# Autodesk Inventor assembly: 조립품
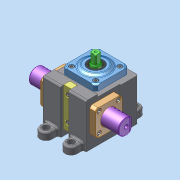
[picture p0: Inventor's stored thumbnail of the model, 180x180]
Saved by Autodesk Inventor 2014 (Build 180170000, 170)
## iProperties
Created: 2024-11
Part Number: 조립품
Document SubType Name: Assembly
Designer: dg
Author: dg
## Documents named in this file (10)
- C:\Users\dg\Desktop\741104V1008\조립품.iam
- C:\Users\dg\Desktop\741104V1008\본체.ipt
- C:\Users\dg\Desktop\741104V1008\가져온 구성요소\피니언 축\피니언 축.ipt
- C:\Users\dg\Desktop\741104V1008\가져온 구성요소\깊음 홈 볼 베어링 6202\깊음 홈 볼 베어링 6202.ipt
- C:\Users\dg\Desktop\741104V1008\가져온 구성요소\커버\커버.ipt
- C:\Users\dg\Desktop\741104V1008\가져온 구성요소\오일 실 15 25 4\오일 실 15 25 4.ipt
- C:\Users\dg\Desktop\741104V1008\가져온 구성요소\육각 소켓 머리 볼트 M4x10\육각 소켓 머리 볼트 M4x10.ipt
- C:\Users\dg\Desktop\741104V1008\가져온 구성요소\수지 부시\수지 부시.ipt
- C:\Users\dg\Desktop\741104V1008\가져온 구성요소\래크\래크.ipt
- C:\Users\dg\Desktop\741104V1008\가져온 구성요소\스톱퍼\스톱퍼.ipt
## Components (1 placed, 1 different names)
1. 피니언 축:1
